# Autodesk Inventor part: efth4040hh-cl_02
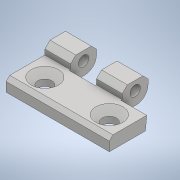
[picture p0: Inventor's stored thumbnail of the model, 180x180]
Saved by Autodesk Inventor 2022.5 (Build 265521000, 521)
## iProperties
Part Number: efth4040hh-cl_02
Material: 一般
Document SubType Name: Modeling
Designer: ImaoCorp
Density: 1 g/cm^3
Appearance: 既定
Author: ImaoCorp
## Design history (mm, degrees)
feature "efth4040hh-cl_02"
node "ソリッド1"
